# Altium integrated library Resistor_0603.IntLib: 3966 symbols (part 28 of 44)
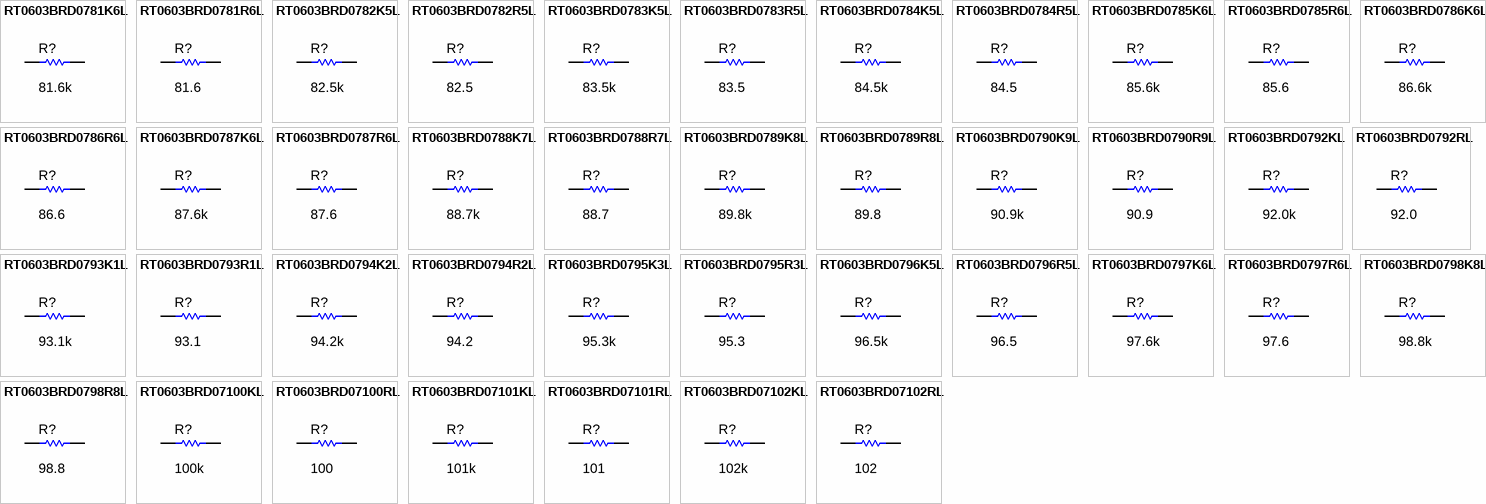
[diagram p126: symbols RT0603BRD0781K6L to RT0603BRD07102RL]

## RT0603BRD0787K6L
designator R?  ValueDisplayed: 87.6k  (hidden comment: RT0603BRD0787K6L)
RES, 87.6 k, 0.1%, 0.1 W, 0603; Manufacturer: Yageo America; CompType: Resistor; Value: 87.6k; Res_ohm: 87600; Value_Code: 87k6; Tolerance_%: 0.1; Value2: 0.1W; VDC_V: 75; TempCo: 25 ppm/C; SizeArea_mm2: 1.28; SizeX_mm: 1.6; SizeY_mm: 0.8; SizeZ_mm: 1; EIA_Code: E192; U/M: EA; AEC Category: Q200
signal-integrity model Resistor
simulation model Resistor
footprint 0603
footprint 0603M
footprint 0603L
footprint 0603_HV
footprint 0603S
pins: 1, 2

## RT0603BRD0787R6L
designator R?  ValueDisplayed: 87.6  (hidden comment: RT0603BRD0787R6L)
RES, 87.6, 0.1%, 0.1 W, 0603; Manufacturer: Yageo America; CompType: Resistor; Value: 87.6; Value_Code: 87R6; Tolerance_%: 0.1; Value2: 0.1W; VDC_V: 75; TempCo: 25 ppm/C; SizeArea_mm2: 1.28; SizeX_mm: 1.6; SizeY_mm: 0.8; SizeZ_mm: 1; EIA_Code: E192; U/M: EA; AEC Category: Q200
signal-integrity model Resistor
simulation model Resistor
footprint 0603
footprint 0603M
footprint 0603L
footprint 0603_HV
footprint 0603S
pins: 1, 2

## RT0603BRD0788K7L
designator R?  ValueDisplayed: 88.7k  (hidden comment: RT0603BRD0788K7L)
RES, 88.7 k, 0.1%, 0.1 W, 0603; Manufacturer: Yageo America; CompType: Resistor; Value: 88.7k; Res_ohm: 88700; Value_Code: 88k7; Tolerance_%: 0.1; Value2: 0.1W; VDC_V: 75; TempCo: 25 ppm/C; SizeArea_mm2: 1.28; SizeX_mm: 1.6; SizeY_mm: 0.8; SizeZ_mm: 1; EIA_Code: E192; U/M: EA; AEC Category: Q200
signal-integrity model Resistor
simulation model Resistor
footprint 0603
footprint 0603M
footprint 0603L
footprint 0603_HV
footprint 0603S
pins: 1, 2

## RT0603BRD0788R7L
designator R?  ValueDisplayed: 88.7  (hidden comment: RT0603BRD0788R7L)
RES, 88.7, 0.1%, 0.1 W, 0603; Manufacturer: Yageo America; CompType: Resistor; Value: 88.7; Value_Code: 88R7; Tolerance_%: 0.1; Value2: 0.1W; VDC_V: 75; TempCo: 25 ppm/C; SizeArea_mm2: 1.28; SizeX_mm: 1.6; SizeY_mm: 0.8; SizeZ_mm: 1; EIA_Code: E192; U/M: EA; AEC Category: Q200
signal-integrity model Resistor
simulation model Resistor
footprint 0603
footprint 0603M
footprint 0603L
footprint 0603_HV
footprint 0603S
pins: 1, 2

## RT0603BRD0789K8L
designator R?  ValueDisplayed: 89.8k  (hidden comment: RT0603BRD0789K8L)
RES, 89.8 k, 0.1%, 0.1 W, 0603; Manufacturer: Yageo America; CompType: Resistor; Value: 89.8k; Res_ohm: 89800; Value_Code: 89k8; Tolerance_%: 0.1; Value2: 0.1W; VDC_V: 75; TempCo: 25 ppm/C; SizeArea_mm2: 1.28; SizeX_mm: 1.6; SizeY_mm: 0.8; SizeZ_mm: 1; EIA_Code: E192; U/M: EA; AEC Category: Q200
signal-integrity model Resistor
simulation model Resistor
footprint 0603
footprint 0603M
footprint 0603L
footprint 0603_HV
footprint 0603S
pins: 1, 2

## RT0603BRD0789R8L
designator R?  ValueDisplayed: 89.8  (hidden comment: RT0603BRD0789R8L)
RES, 89.8, 0.1%, 0.1 W, 0603; Manufacturer: Yageo America; CompType: Resistor; Value: 89.8; Value_Code: 89R8; Tolerance_%: 0.1; Value2: 0.1W; VDC_V: 75; TempCo: 25 ppm/C; SizeArea_mm2: 1.28; SizeX_mm: 1.6; SizeY_mm: 0.8; SizeZ_mm: 1; EIA_Code: E192; U/M: EA; AEC Category: Q200
signal-integrity model Resistor
simulation model Resistor
footprint 0603
footprint 0603M
footprint 0603L
footprint 0603_HV
footprint 0603S
pins: 1, 2

## RT0603BRD0790K9L
designator R?  ValueDisplayed: 90.9k  (hidden comment: RT0603BRD0790K9L)
RES, 90.9 k, 0.1%, 0.1 W, 0603; Manufacturer: Yageo America; CompType: Resistor; Value: 90.9k; Res_ohm: 90900; Value_Code: 90k9; Tolerance_%: 0.1; Value2: 0.1W; VDC_V: 75; TempCo: 25 ppm/C; SizeArea_mm2: 1.28; SizeX_mm: 1.6; SizeY_mm: 0.8; SizeZ_mm: 1; EIA_Code: E192; U/M: EA; AEC Category: Q200
signal-integrity model Resistor
simulation model Resistor
footprint 0603
footprint 0603M
footprint 0603L
footprint 0603_HV
footprint 0603S
pins: 1, 2

## RT0603BRD0790R9L
designator R?  ValueDisplayed: 90.9  (hidden comment: RT0603BRD0790R9L)
RES, 90.9, 0.1%, 0.1 W, 0603; Manufacturer: Yageo America; CompType: Resistor; Value: 90.9; Value_Code: 90R9; Tolerance_%: 0.1; Value2: 0.1W; VDC_V: 75; TempCo: 25 ppm/C; SizeArea_mm2: 1.28; SizeX_mm: 1.6; SizeY_mm: 0.8; SizeZ_mm: 1; EIA_Code: E192; U/M: EA; AEC Category: Q200
signal-integrity model Resistor
simulation model Resistor
footprint 0603
footprint 0603M
footprint 0603L
footprint 0603_HV
footprint 0603S
pins: 1, 2

## RT0603BRD0792KL
designator R?  ValueDisplayed: 92.0k  (hidden comment: RT0603BRD0792KL)
RES, 92.0 k, 0.1%, 0.1 W, 0603; Manufacturer: Yageo America; CompType: Resistor; Value: 92.0k; Res_ohm: 92000; Value_Code: 92k0; Tolerance_%: 0.1; Value2: 0.1W; VDC_V: 75; TempCo: 25 ppm/C; SizeArea_mm2: 1.28; SizeX_mm: 1.6; SizeY_mm: 0.8; SizeZ_mm: 1; EIA_Code: E192; U/M: EA; AEC Category: Q200
signal-integrity model Resistor
simulation model Resistor
footprint 0603
footprint 0603M
footprint 0603L
footprint 0603_HV
footprint 0603S
pins: 1, 2

## RT0603BRD0792RL
designator R?  ValueDisplayed: 92.0  (hidden comment: RT0603BRD0792RL)
RES, 92.0, 0.1%, 0.1 W, 0603; Manufacturer: Yageo America; CompType: Resistor; Value: 92.0; Res_ohm: 92; Value_Code: 92R0; Tolerance_%: 0.1; Value2: 0.1W; VDC_V: 75; TempCo: 25 ppm/C; SizeArea_mm2: 1.28; SizeX_mm: 1.6; SizeY_mm: 0.8; SizeZ_mm: 1; EIA_Code: E192; U/M: EA; AEC Category: Q200
signal-integrity model Resistor
simulation model Resistor
footprint 0603
footprint 0603M
footprint 0603L
footprint 0603_HV
footprint 0603S
pins: 1, 2

## RT0603BRD0793K1L
designator R?  ValueDisplayed: 93.1k  (hidden comment: RT0603BRD0793K1L)
RES, 93.1 k, 0.1%, 0.1 W, 0603; Manufacturer: Yageo America; CompType: Resistor; Value: 93.1k; Res_ohm: 93100; Value_Code: 93k1; Tolerance_%: 0.1; Value2: 0.1W; VDC_V: 75; TempCo: 25 ppm/C; SizeArea_mm2: 1.28; SizeX_mm: 1.6; SizeY_mm: 0.8; SizeZ_mm: 1; EIA_Code: E192; U/M: EA; AEC Category: Q200
signal-integrity model Resistor
simulation model Resistor
footprint 0603
footprint 0603M
footprint 0603L
footprint 0603_HV
footprint 0603S
pins: 1, 2

## RT0603BRD0793R1L
designator R?  ValueDisplayed: 93.1  (hidden comment: RT0603BRD0793R1L)
RES, 93.1, 0.1%, 0.1 W, 0603; Manufacturer: Yageo America; CompType: Resistor; Value: 93.1; Value_Code: 93R1; Tolerance_%: 0.1; Value2: 0.1W; VDC_V: 75; TempCo: 25 ppm/C; SizeArea_mm2: 1.28; SizeX_mm: 1.6; SizeY_mm: 0.8; SizeZ_mm: 1; EIA_Code: E192; U/M: EA; AEC Category: Q200
signal-integrity model Resistor
simulation model Resistor
footprint 0603
footprint 0603M
footprint 0603L
footprint 0603_HV
footprint 0603S
pins: 1, 2

## RT0603BRD0794K2L
designator R?  ValueDisplayed: 94.2k  (hidden comment: RT0603BRD0794K2L)
RES, 94.2 k, 0.1%, 0.1 W, 0603; Manufacturer: Yageo America; CompType: Resistor; Value: 94.2k; Res_ohm: 94200; Value_Code: 94k2; Tolerance_%: 0.1; Value2: 0.1W; VDC_V: 75; TempCo: 25 ppm/C; SizeArea_mm2: 1.28; SizeX_mm: 1.6; SizeY_mm: 0.8; SizeZ_mm: 1; EIA_Code: E192; U/M: EA; AEC Category: Q200
signal-integrity model Resistor
simulation model Resistor
footprint 0603
footprint 0603M
footprint 0603L
footprint 0603_HV
footprint 0603S
pins: 1, 2

## RT0603BRD0794R2L
designator R?  ValueDisplayed: 94.2  (hidden comment: RT0603BRD0794R2L)
RES, 94.2, 0.1%, 0.1 W, 0603; Manufacturer: Yageo America; CompType: Resistor; Value: 94.2; Value_Code: 94R2; Tolerance_%: 0.1; Value2: 0.1W; VDC_V: 75; TempCo: 25 ppm/C; SizeArea_mm2: 1.28; SizeX_mm: 1.6; SizeY_mm: 0.8; SizeZ_mm: 1; EIA_Code: E192; U/M: EA; AEC Category: Q200
signal-integrity model Resistor
simulation model Resistor
footprint 0603
footprint 0603M
footprint 0603L
footprint 0603_HV
footprint 0603S
pins: 1, 2

## RT0603BRD0795K3L
designator R?  ValueDisplayed: 95.3k  (hidden comment: RT0603BRD0795K3L)
RES, 95.3 k, 0.1%, 0.1 W, 0603; Manufacturer: Yageo America; CompType: Resistor; Value: 95.3k; Res_ohm: 95300; Value_Code: 95k3; Tolerance_%: 0.1; Value2: 0.1W; VDC_V: 75; TempCo: 25 ppm/C; SizeArea_mm2: 1.28; SizeX_mm: 1.6; SizeY_mm: 0.8; SizeZ_mm: 1; EIA_Code: E192; U/M: EA; AEC Category: Q200
signal-integrity model Resistor
simulation model Resistor
footprint 0603
footprint 0603M
footprint 0603L
footprint 0603_HV
footprint 0603S
pins: 1, 2

## RT0603BRD0795R3L
designator R?  ValueDisplayed: 95.3  (hidden comment: RT0603BRD0795R3L)
RES, 95.3, 0.1%, 0.1 W, 0603; Manufacturer: Yageo America; CompType: Resistor; Value: 95.3; Value_Code: 95R3; Tolerance_%: 0.1; Value2: 0.1W; VDC_V: 75; TempCo: 25 ppm/C; SizeArea_mm2: 1.28; SizeX_mm: 1.6; SizeY_mm: 0.8; SizeZ_mm: 1; EIA_Code: E192; U/M: EA; AEC Category: Q200
signal-integrity model Resistor
simulation model Resistor
footprint 0603
footprint 0603M
footprint 0603L
footprint 0603_HV
footprint 0603S
pins: 1, 2

## RT0603BRD0796K5L
designator R?  ValueDisplayed: 96.5k  (hidden comment: RT0603BRD0796K5L)
RES, 96.5 k, 0.1%, 0.1 W, 0603; Manufacturer: Yageo America; CompType: Resistor; Value: 96.5k; Res_ohm: 96500; Value_Code: 96k5; Tolerance_%: 0.1; Value2: 0.1W; VDC_V: 75; TempCo: 25 ppm/C; SizeArea_mm2: 1.28; SizeX_mm: 1.6; SizeY_mm: 0.8; SizeZ_mm: 1; EIA_Code: E192; U/M: EA; AEC Category: Q200
signal-integrity model Resistor
simulation model Resistor
footprint 0603
footprint 0603M
footprint 0603L
footprint 0603_HV
footprint 0603S
pins: 1, 2

## RT0603BRD0796R5L
designator R?  ValueDisplayed: 96.5  (hidden comment: RT0603BRD0796R5L)
RES, 96.5, 0.1%, 0.1 W, 0603; Manufacturer: Yageo America; CompType: Resistor; Value: 96.5; Value_Code: 96R5; Tolerance_%: 0.1; Value2: 0.1W; VDC_V: 75; TempCo: 25 ppm/C; SizeArea_mm2: 1.28; SizeX_mm: 1.6; SizeY_mm: 0.8; SizeZ_mm: 1; EIA_Code: E192; U/M: EA; AEC Category: Q200
signal-integrity model Resistor
simulation model Resistor
footprint 0603
footprint 0603M
footprint 0603L
footprint 0603_HV
footprint 0603S
pins: 1, 2

## RT0603BRD0797K6L
designator R?  ValueDisplayed: 97.6k  (hidden comment: RT0603BRD0797K6L)
RES, 97.6 k, 0.1%, 0.1 W, 0603; Manufacturer: Yageo America; CompType: Resistor; Value: 97.6k; Res_ohm: 97600; Value_Code: 97k6; Tolerance_%: 0.1; Value2: 0.1W; VDC_V: 75; TempCo: 25 ppm/C; SizeArea_mm2: 1.28; SizeX_mm: 1.6; SizeY_mm: 0.8; SizeZ_mm: 1; EIA_Code: E192; U/M: EA; AEC Category: Q200
signal-integrity model Resistor
simulation model Resistor
footprint 0603
footprint 0603M
footprint 0603L
footprint 0603_HV
footprint 0603S
pins: 1, 2

## RT0603BRD0797R6L
designator R?  ValueDisplayed: 97.6  (hidden comment: RT0603BRD0797R6L)
RES, 97.6, 0.1%, 0.1 W, 0603; Manufacturer: Yageo America; CompType: Resistor; Value: 97.6; Value_Code: 97R6; Tolerance_%: 0.1; Value2: 0.1W; VDC_V: 75; TempCo: 25 ppm/C; SizeArea_mm2: 1.28; SizeX_mm: 1.6; SizeY_mm: 0.8; SizeZ_mm: 1; EIA_Code: E192; U/M: EA; AEC Category: Q200
signal-integrity model Resistor
simulation model Resistor
footprint 0603
footprint 0603M
footprint 0603L
footprint 0603_HV
footprint 0603S
pins: 1, 2

## RT0603BRD0798K8L
designator R?  ValueDisplayed: 98.8k  (hidden comment: RT0603BRD0798K8L)
RES, 98.8 k, 0.1%, 0.1 W, 0603; Manufacturer: Yageo America; CompType: Resistor; Value: 98.8k; Res_ohm: 98800; Value_Code: 98k8; Tolerance_%: 0.1; Value2: 0.1W; VDC_V: 75; TempCo: 25 ppm/C; SizeArea_mm2: 1.28; SizeX_mm: 1.6; SizeY_mm: 0.8; SizeZ_mm: 1; EIA_Code: E192; U/M: EA; AEC Category: Q200
signal-integrity model Resistor
simulation model Resistor
footprint 0603
footprint 0603M
footprint 0603L
footprint 0603_HV
footprint 0603S
pins: 1, 2

## RT0603BRD0798R8L
designator R?  ValueDisplayed: 98.8  (hidden comment: RT0603BRD0798R8L)
RES, 98.8, 0.1%, 0.1 W, 0603; Manufacturer: Yageo America; CompType: Resistor; Value: 98.8; Value_Code: 98R8; Tolerance_%: 0.1; Value2: 0.1W; VDC_V: 75; TempCo: 25 ppm/C; SizeArea_mm2: 1.28; SizeX_mm: 1.6; SizeY_mm: 0.8; SizeZ_mm: 1; EIA_Code: E192; U/M: EA; AEC Category: Q200
signal-integrity model Resistor
simulation model Resistor
footprint 0603
footprint 0603M
footprint 0603L
footprint 0603_HV
footprint 0603S
pins: 1, 2

## RT0603BRD07100KL
designator R?  ValueDisplayed: 100k  (hidden comment: RT0603BRD07100KL)
RES, 100 k, 0.1%, 0.1 W, 0603; Manufacturer: Yageo America; CompType: Resistor; Value: 100k; Res_ohm: 100000; Tolerance_%: 0.1; Value2: 0.1W; VDC_V: 75; TempCo: 25 ppm/C; SizeArea_mm2: 1.28; SizeX_mm: 1.6; SizeY_mm: 0.8; SizeZ_mm: 1; EIA_Code: E192; U/M: EA; AEC Category: Q200; Green_Lifecycle: Active; Green_REACh: Passed
signal-integrity model Resistor
simulation model Resistor
footprint 0603
footprint 0603M
footprint 0603L
footprint 0603_HV
footprint 0603S
pins: 1, 2

## RT0603BRD07100RL
designator R?  ValueDisplayed: 100  (hidden comment: RT0603BRD07100RL)
RES, 100, 0.1%, 0.1 W, 0603; Manufacturer: Yageo America; CompType: Resistor; Value: 100; Value_Code: 100R; Tolerance_%: 0.1; Value2: 0.1W; VDC_V: 75; TempCo: 25 ppm/C; SizeArea_mm2: 1.28; SizeX_mm: 1.6; SizeY_mm: 0.8; SizeZ_mm: 1; EIA_Code: E192; U/M: EA; AEC Category: Q200
signal-integrity model Resistor
simulation model Resistor
footprint 0603
footprint 0603M
footprint 0603L
footprint 0603_HV
footprint 0603S
pins: 1, 2

## RT0603BRD07101KL
designator R?  ValueDisplayed: 101k  (hidden comment: RT0603BRD07101KL)
RES, 101 k, 0.1%, 0.1 W, 0603; Manufacturer: Yageo America; CompType: Resistor; Value: 101k; Res_ohm: 101000; Tolerance_%: 0.1; Value2: 0.1W; VDC_V: 75; TempCo: 25 ppm/C; SizeArea_mm2: 1.28; SizeX_mm: 1.6; SizeY_mm: 0.8; SizeZ_mm: 1; EIA_Code: E192; U/M: EA; AEC Category: Q200
signal-integrity model Resistor
simulation model Resistor
footprint 0603
footprint 0603M
footprint 0603L
footprint 0603_HV
footprint 0603S
pins: 1, 2

## RT0603BRD07101RL
designator R?  ValueDisplayed: 101  (hidden comment: RT0603BRD07101RL)
RES, 101, 0.1%, 0.1 W, 0603; Manufacturer: Yageo America; CompType: Resistor; Value: 101; Value_Code: 101R; Tolerance_%: 0.1; Value2: 0.1W; VDC_V: 75; TempCo: 25 ppm/C; SizeArea_mm2: 1.28; SizeX_mm: 1.6; SizeY_mm: 0.8; SizeZ_mm: 1; EIA_Code: E192; U/M: EA; AEC Category: Q200
signal-integrity model Resistor
simulation model Resistor
footprint 0603
footprint 0603M
footprint 0603L
footprint 0603_HV
footprint 0603S
pins: 1, 2

## RT0603BRD07102KL
designator R?  ValueDisplayed: 102k  (hidden comment: RT0603BRD07102KL)
RES, 102 k, 0.1%, 0.1 W, 0603; Manufacturer: Yageo America; CompType: Resistor; Value: 102k; Res_ohm: 102000; Tolerance_%: 0.1; Value2: 0.1W; VDC_V: 75; TempCo: 25 ppm/C; SizeArea_mm2: 1.28; SizeX_mm: 1.6; SizeY_mm: 0.8; SizeZ_mm: 1; EIA_Code: E192; U/M: EA; AEC Category: Q200
signal-integrity model Resistor
simulation model Resistor
footprint 0603
footprint 0603M
footprint 0603L
footprint 0603_HV
footprint 0603S
pins: 1, 2

## RT0603BRD07102RL
designator R?  ValueDisplayed: 102  (hidden comment: RT0603BRD07102RL)
RES, 102, 0.1%, 0.1 W, 0603; Manufacturer: Yageo America; CompType: Resistor; Value: 102; Value_Code: 102R; Tolerance_%: 0.1; Value2: 0.1W; VDC_V: 75; TempCo: 25 ppm/C; SizeArea_mm2: 1.28; SizeX_mm: 1.6; SizeY_mm: 0.8; SizeZ_mm: 1; EIA_Code: E192; U/M: EA; AEC Category: Q200
signal-integrity model Resistor
simulation model Resistor
footprint 0603
footprint 0603M
footprint 0603L
footprint 0603_HV
footprint 0603S
pins: 1, 2

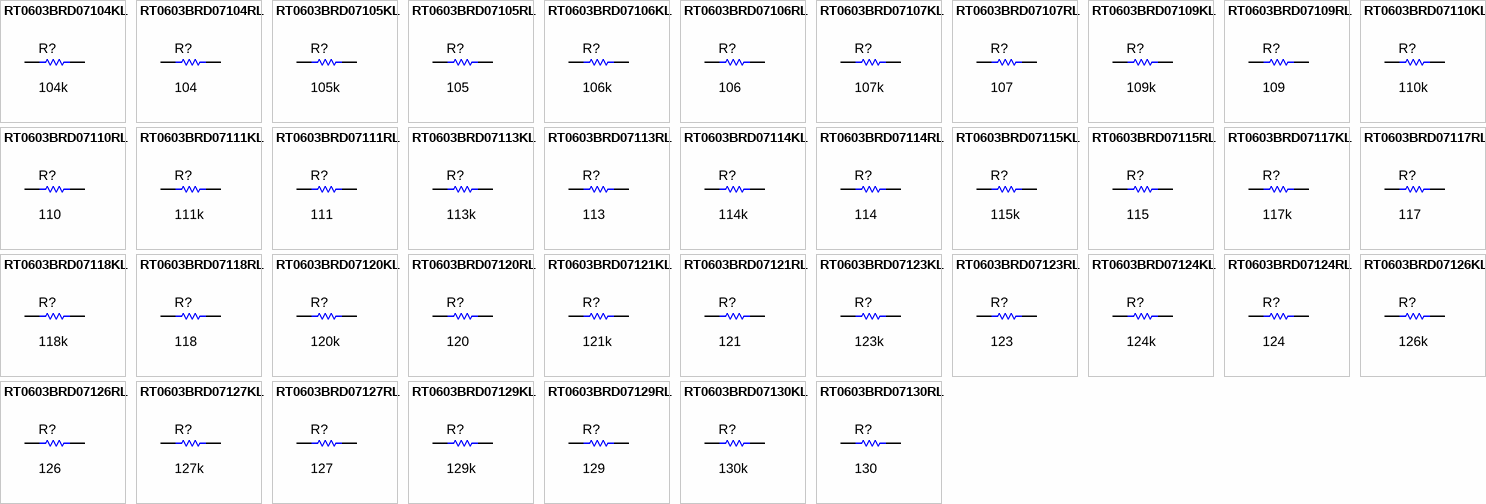
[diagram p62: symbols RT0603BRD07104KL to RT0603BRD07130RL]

## RT0603BRD07104KL
designator R?  ValueDisplayed: 104k  (hidden comment: RT0603BRD07104KL)
RES, 104 k, 0.1%, 0.1 W, 0603; Manufacturer: Yageo America; CompType: Resistor; Value: 104k; Res_ohm: 104000; Tolerance_%: 0.1; Value2: 0.1W; VDC_V: 75; TempCo: 25 ppm/C; SizeArea_mm2: 1.28; SizeX_mm: 1.6; SizeY_mm: 0.8; SizeZ_mm: 1; EIA_Code: E192; U/M: EA; AEC Category: Q200
signal-integrity model Resistor
simulation model Resistor
footprint 0603
footprint 0603M
footprint 0603L
footprint 0603_HV
footprint 0603S
pins: 1, 2

## RT0603BRD07104RL
designator R?  ValueDisplayed: 104  (hidden comment: RT0603BRD07104RL)
RES, 104, 0.1%, 0.1 W, 0603; Manufacturer: Yageo America; CompType: Resistor; Value: 104; Value_Code: 104R; Tolerance_%: 0.1; Value2: 0.1W; VDC_V: 75; TempCo: 25 ppm/C; SizeArea_mm2: 1.28; SizeX_mm: 1.6; SizeY_mm: 0.8; SizeZ_mm: 1; EIA_Code: E192; U/M: EA; AEC Category: Q200
signal-integrity model Resistor
simulation model Resistor
footprint 0603
footprint 0603M
footprint 0603L
footprint 0603_HV
footprint 0603S
pins: 1, 2

## RT0603BRD07105KL
designator R?  ValueDisplayed: 105k  (hidden comment: RT0603BRD07105KL)
RES, 105 k, 0.1%, 0.1 W, 0603; Manufacturer: Yageo America; CompType: Resistor; Value: 105k; Res_ohm: 105000; Tolerance_%: 0.1; Value2: 0.1W; VDC_V: 75; TempCo: 25 ppm/C; SizeArea_mm2: 1.28; SizeX_mm: 1.6; SizeY_mm: 0.8; SizeZ_mm: 1; EIA_Code: E192; U/M: EA; AEC Category: Q200
signal-integrity model Resistor
simulation model Resistor
footprint 0603
footprint 0603M
footprint 0603L
footprint 0603_HV
footprint 0603S
pins: 1, 2

## RT0603BRD07105RL
designator R?  ValueDisplayed: 105  (hidden comment: RT0603BRD07105RL)
RES, 105, 0.1%, 0.1 W, 0603; Manufacturer: Yageo America; CompType: Resistor; Value: 105; Value_Code: 105R; Tolerance_%: 0.1; Value2: 0.1W; VDC_V: 75; TempCo: 25 ppm/C; SizeArea_mm2: 1.28; SizeX_mm: 1.6; SizeY_mm: 0.8; SizeZ_mm: 1; EIA_Code: E192; U/M: EA; AEC Category: Q200
signal-integrity model Resistor
simulation model Resistor
footprint 0603
footprint 0603M
footprint 0603L
footprint 0603_HV
footprint 0603S
pins: 1, 2

## RT0603BRD07106KL
designator R?  ValueDisplayed: 106k  (hidden comment: RT0603BRD07106KL)
RES, 106 k, 0.1%, 0.1 W, 0603; Manufacturer: Yageo America; CompType: Resistor; Value: 106k; Res_ohm: 106000; Tolerance_%: 0.1; Value2: 0.1W; VDC_V: 75; TempCo: 25 ppm/C; SizeArea_mm2: 1.28; SizeX_mm: 1.6; SizeY_mm: 0.8; SizeZ_mm: 1; EIA_Code: E192; U/M: EA; AEC Category: Q200
signal-integrity model Resistor
simulation model Resistor
footprint 0603
footprint 0603M
footprint 0603L
footprint 0603_HV
footprint 0603S
pins: 1, 2

## RT0603BRD07106RL
designator R?  ValueDisplayed: 106  (hidden comment: RT0603BRD07106RL)
RES, 106, 0.1%, 0.1 W, 0603; Manufacturer: Yageo America; CompType: Resistor; Value: 106; Value_Code: 106R; Tolerance_%: 0.1; Value2: 0.1W; VDC_V: 75; TempCo: 25 ppm/C; SizeArea_mm2: 1.28; SizeX_mm: 1.6; SizeY_mm: 0.8; SizeZ_mm: 1; EIA_Code: E192; U/M: EA; AEC Category: Q200
signal-integrity model Resistor
simulation model Resistor
footprint 0603
footprint 0603M
footprint 0603L
footprint 0603_HV
footprint 0603S
pins: 1, 2

## RT0603BRD07107KL
designator R?  ValueDisplayed: 107k  (hidden comment: RT0603BRD07107KL)
RES, 107 k, 0.1%, 0.1 W, 0603; Manufacturer: Yageo America; CompType: Resistor; Value: 107k; Res_ohm: 107000; Tolerance_%: 0.1; Value2: 0.1W; VDC_V: 75; TempCo: 25 ppm/C; SizeArea_mm2: 1.28; SizeX_mm: 1.6; SizeY_mm: 0.8; SizeZ_mm: 1; EIA_Code: E192; U/M: EA; AEC Category: Q200
signal-integrity model Resistor
simulation model Resistor
footprint 0603
footprint 0603M
footprint 0603L
footprint 0603_HV
footprint 0603S
pins: 1, 2

## RT0603BRD07107RL
designator R?  ValueDisplayed: 107  (hidden comment: RT0603BRD07107RL)
RES, 107, 0.1%, 0.1 W, 0603; Manufacturer: Yageo America; CompType: Resistor; Value: 107; Value_Code: 107R; Tolerance_%: 0.1; Value2: 0.1W; VDC_V: 75; TempCo: 25 ppm/C; SizeArea_mm2: 1.28; SizeX_mm: 1.6; SizeY_mm: 0.8; SizeZ_mm: 1; EIA_Code: E192; U/M: EA; AEC Category: Q200
signal-integrity model Resistor
simulation model Resistor
footprint 0603
footprint 0603M
footprint 0603L
footprint 0603_HV
footprint 0603S
pins: 1, 2

## RT0603BRD07109KL
designator R?  ValueDisplayed: 109k  (hidden comment: RT0603BRD07109KL)
RES, 109 k, 0.1%, 0.1 W, 0603; Manufacturer: Yageo America; CompType: Resistor; Value: 109k; Res_ohm: 109000; Tolerance_%: 0.1; Value2: 0.1W; VDC_V: 75; TempCo: 25 ppm/C; SizeArea_mm2: 1.28; SizeX_mm: 1.6; SizeY_mm: 0.8; SizeZ_mm: 1; EIA_Code: E192; U/M: EA; AEC Category: Q200
signal-integrity model Resistor
simulation model Resistor
footprint 0603
footprint 0603M
footprint 0603L
footprint 0603_HV
footprint 0603S
pins: 1, 2

## RT0603BRD07109RL
designator R?  ValueDisplayed: 109  (hidden comment: RT0603BRD07109RL)
RES, 109, 0.1%, 0.1 W, 0603; Manufacturer: Yageo America; CompType: Resistor; Value: 109; Value_Code: 109R; Tolerance_%: 0.1; Value2: 0.1W; VDC_V: 75; TempCo: 25 ppm/C; SizeArea_mm2: 1.28; SizeX_mm: 1.6; SizeY_mm: 0.8; SizeZ_mm: 1; EIA_Code: E192; U/M: EA; AEC Category: Q200
signal-integrity model Resistor
simulation model Resistor
footprint 0603
footprint 0603M
footprint 0603L
footprint 0603_HV
footprint 0603S
pins: 1, 2

## RT0603BRD07110KL
designator R?  ValueDisplayed: 110k  (hidden comment: RT0603BRD07110KL)
RES, 110 k, 0.1%, 0.1 W, 0603; Manufacturer: Yageo America; CompType: Resistor; Value: 110k; Res_ohm: 110000; Tolerance_%: 0.1; Value2: 0.1W; VDC_V: 75; TempCo: 25 ppm/C; SizeArea_mm2: 1.28; SizeX_mm: 1.6; SizeY_mm: 0.8; SizeZ_mm: 1; EIA_Code: E192; U/M: EA; AEC Category: Q200
signal-integrity model Resistor
simulation model Resistor
footprint 0603
footprint 0603M
footprint 0603L
footprint 0603_HV
footprint 0603S
pins: 1, 2

## RT0603BRD07110RL
designator R?  ValueDisplayed: 110  (hidden comment: RT0603BRD07110RL)
RES, 110, 0.1%, 0.1 W, 0603; Manufacturer: Yageo America; CompType: Resistor; Value: 110; Value_Code: 110R; Tolerance_%: 0.1; Value2: 0.1W; VDC_V: 75; TempCo: 25 ppm/C; SizeArea_mm2: 1.28; SizeX_mm: 1.6; SizeY_mm: 0.8; SizeZ_mm: 1; EIA_Code: E192; U/M: EA; AEC Category: Q200
signal-integrity model Resistor
simulation model Resistor
footprint 0603
footprint 0603M
footprint 0603L
footprint 0603_HV
footprint 0603S
pins: 1, 2

## RT0603BRD07111KL
designator R?  ValueDisplayed: 111k  (hidden comment: RT0603BRD07111KL)
RES, 111 k, 0.1%, 0.1 W, 0603; Manufacturer: Yageo America; CompType: Resistor; Value: 111k; Res_ohm: 111000; Tolerance_%: 0.1; Value2: 0.1W; VDC_V: 75; TempCo: 25 ppm/C; SizeArea_mm2: 1.28; SizeX_mm: 1.6; SizeY_mm: 0.8; SizeZ_mm: 1; EIA_Code: E192; U/M: EA; AEC Category: Q200
signal-integrity model Resistor
simulation model Resistor
footprint 0603
footprint 0603M
footprint 0603L
footprint 0603_HV
footprint 0603S
pins: 1, 2

## RT0603BRD07111RL
designator R?  ValueDisplayed: 111  (hidden comment: RT0603BRD07111RL)
RES, 111, 0.1%, 0.1 W, 0603; Manufacturer: Yageo America; CompType: Resistor; Value: 111; Value_Code: 111R; Tolerance_%: 0.1; Value2: 0.1W; VDC_V: 75; TempCo: 25 ppm/C; SizeArea_mm2: 1.28; SizeX_mm: 1.6; SizeY_mm: 0.8; SizeZ_mm: 1; EIA_Code: E192; U/M: EA; AEC Category: Q200
signal-integrity model Resistor
simulation model Resistor
footprint 0603
footprint 0603M
footprint 0603L
footprint 0603_HV
footprint 0603S
pins: 1, 2

## RT0603BRD07113KL
designator R?  ValueDisplayed: 113k  (hidden comment: RT0603BRD07113KL)
RES, 113 k, 0.1%, 0.1 W, 0603; Manufacturer: Yageo America; CompType: Resistor; Value: 113k; Res_ohm: 113000; Tolerance_%: 0.1; Value2: 0.1W; VDC_V: 75; TempCo: 25 ppm/C; SizeArea_mm2: 1.28; SizeX_mm: 1.6; SizeY_mm: 0.8; SizeZ_mm: 1; EIA_Code: E192; U/M: EA; AEC Category: Q200
signal-integrity model Resistor
simulation model Resistor
footprint 0603
footprint 0603M
footprint 0603L
footprint 0603_HV
footprint 0603S
pins: 1, 2

## RT0603BRD07113RL
designator R?  ValueDisplayed: 113  (hidden comment: RT0603BRD07113RL)
RES, 113, 0.1%, 0.1 W, 0603; Manufacturer: Yageo America; CompType: Resistor; Value: 113; Value_Code: 113R; Tolerance_%: 0.1; Value2: 0.1W; VDC_V: 75; TempCo: 25 ppm/C; SizeArea_mm2: 1.28; SizeX_mm: 1.6; SizeY_mm: 0.8; SizeZ_mm: 1; EIA_Code: E192; U/M: EA; AEC Category: Q200
signal-integrity model Resistor
simulation model Resistor
footprint 0603
footprint 0603M
footprint 0603L
footprint 0603_HV
footprint 0603S
pins: 1, 2

## RT0603BRD07114KL
designator R?  ValueDisplayed: 114k  (hidden comment: RT0603BRD07114KL)
RES, 114 k, 0.1%, 0.1 W, 0603; Manufacturer: Yageo America; CompType: Resistor; Value: 114k; Res_ohm: 114000; Tolerance_%: 0.1; Value2: 0.1W; VDC_V: 75; TempCo: 25 ppm/C; SizeArea_mm2: 1.28; SizeX_mm: 1.6; SizeY_mm: 0.8; SizeZ_mm: 1; EIA_Code: E192; U/M: EA; AEC Category: Q200
signal-integrity model Resistor
simulation model Resistor
footprint 0603
footprint 0603M
footprint 0603L
footprint 0603_HV
footprint 0603S
pins: 1, 2

## RT0603BRD07114RL
designator R?  ValueDisplayed: 114  (hidden comment: RT0603BRD07114RL)
RES, 114, 0.1%, 0.1 W, 0603; Manufacturer: Yageo America; CompType: Resistor; Value: 114; Value_Code: 114R; Tolerance_%: 0.1; Value2: 0.1W; VDC_V: 75; TempCo: 25 ppm/C; SizeArea_mm2: 1.28; SizeX_mm: 1.6; SizeY_mm: 0.8; SizeZ_mm: 1; EIA_Code: E192; U/M: EA; AEC Category: Q200
signal-integrity model Resistor
simulation model Resistor
footprint 0603
footprint 0603M
footprint 0603L
footprint 0603_HV
footprint 0603S
pins: 1, 2

## RT0603BRD07115KL
designator R?  ValueDisplayed: 115k  (hidden comment: RT0603BRD07115KL)
RES, 115 k, 0.1%, 0.1 W, 0603; Manufacturer: Yageo America; CompType: Resistor; Value: 115k; Res_ohm: 115000; Tolerance_%: 0.1; Value2: 0.1W; VDC_V: 75; TempCo: 25 ppm/C; SizeArea_mm2: 1.28; SizeX_mm: 1.6; SizeY_mm: 0.8; SizeZ_mm: 1; EIA_Code: E192; U/M: EA; AEC Category: Q200
signal-integrity model Resistor
simulation model Resistor
footprint 0603
footprint 0603M
footprint 0603L
footprint 0603_HV
footprint 0603S
pins: 1, 2

## RT0603BRD07115RL
designator R?  ValueDisplayed: 115  (hidden comment: RT0603BRD07115RL)
RES, 115, 0.1%, 0.1 W, 0603; Manufacturer: Yageo America; CompType: Resistor; Value: 115; Value_Code: 115R; Tolerance_%: 0.1; Value2: 0.1W; VDC_V: 75; TempCo: 25 ppm/C; SizeArea_mm2: 1.28; SizeX_mm: 1.6; SizeY_mm: 0.8; SizeZ_mm: 1; EIA_Code: E192; U/M: EA; AEC Category: Q200
signal-integrity model Resistor
simulation model Resistor
footprint 0603
footprint 0603M
footprint 0603L
footprint 0603_HV
footprint 0603S
pins: 1, 2

## RT0603BRD07117KL
designator R?  ValueDisplayed: 117k  (hidden comment: RT0603BRD07117KL)
RES, 117 k, 0.1%, 0.1 W, 0603; Manufacturer: Yageo America; CompType: Resistor; Value: 117k; Res_ohm: 117000; Tolerance_%: 0.1; Value2: 0.1W; VDC_V: 75; TempCo: 25 ppm/C; SizeArea_mm2: 1.28; SizeX_mm: 1.6; SizeY_mm: 0.8; SizeZ_mm: 1; EIA_Code: E192; U/M: EA; AEC Category: Q200
signal-integrity model Resistor
simulation model Resistor
footprint 0603
footprint 0603M
footprint 0603L
footprint 0603_HV
footprint 0603S
pins: 1, 2

## RT0603BRD07117RL
designator R?  ValueDisplayed: 117  (hidden comment: RT0603BRD07117RL)
RES, 117, 0.1%, 0.1 W, 0603; Manufacturer: Yageo America; CompType: Resistor; Value: 117; Value_Code: 117R; Tolerance_%: 0.1; Value2: 0.1W; VDC_V: 75; TempCo: 25 ppm/C; SizeArea_mm2: 1.28; SizeX_mm: 1.6; SizeY_mm: 0.8; SizeZ_mm: 1; EIA_Code: E192; U/M: EA; AEC Category: Q200
signal-integrity model Resistor
simulation model Resistor
footprint 0603
footprint 0603M
footprint 0603L
footprint 0603_HV
footprint 0603S
pins: 1, 2

## RT0603BRD07118KL
designator R?  ValueDisplayed: 118k  (hidden comment: RT0603BRD07118KL)
RES, 118 k, 0.1%, 0.1 W, 0603; Manufacturer: Yageo America; CompType: Resistor; Value: 118k; Res_ohm: 118000; Tolerance_%: 0.1; Value2: 0.1W; VDC_V: 75; TempCo: 25 ppm/C; SizeArea_mm2: 1.28; SizeX_mm: 1.6; SizeY_mm: 0.8; SizeZ_mm: 1; EIA_Code: E192; U/M: EA; AEC Category: Q200
signal-integrity model Resistor
simulation model Resistor
footprint 0603
footprint 0603M
footprint 0603L
footprint 0603_HV
footprint 0603S
pins: 1, 2

## RT0603BRD07118RL
designator R?  ValueDisplayed: 118  (hidden comment: RT0603BRD07118RL)
RES, 118, 0.1%, 0.1 W, 0603; Manufacturer: Yageo America; CompType: Resistor; Value: 118; Value_Code: 118R; Tolerance_%: 0.1; Value2: 0.1W; VDC_V: 75; TempCo: 25 ppm/C; SizeArea_mm2: 1.28; SizeX_mm: 1.6; SizeY_mm: 0.8; SizeZ_mm: 1; EIA_Code: E192; U/M: EA; AEC Category: Q200
signal-integrity model Resistor
simulation model Resistor
footprint 0603
footprint 0603M
footprint 0603L
footprint 0603_HV
footprint 0603S
pins: 1, 2

## RT0603BRD07120KL
designator R?  ValueDisplayed: 120k  (hidden comment: RT0603BRD07120KL)
RES, 120 k, 0.1%, 0.1 W, 0603; Manufacturer: Yageo America; CompType: Resistor; Value: 120k; Res_ohm: 120000; Tolerance_%: 0.1; Value2: 0.1W; VDC_V: 75; TempCo: 25 ppm/C; SizeArea_mm2: 1.28; SizeX_mm: 1.6; SizeY_mm: 0.8; SizeZ_mm: 1; EIA_Code: E192; U/M: EA; AEC Category: Q200
signal-integrity model Resistor
simulation model Resistor
footprint 0603
footprint 0603M
footprint 0603L
footprint 0603_HV
footprint 0603S
pins: 1, 2

## RT0603BRD07120RL
designator R?  ValueDisplayed: 120  (hidden comment: RT0603BRD07120RL)
RES, 120, 0.1%, 0.1 W, 0603; Manufacturer: Yageo America; CompType: Resistor; Value: 120; Value_Code: 120R; Tolerance_%: 0.1; Value2: 0.1W; VDC_V: 75; TempCo: 25 ppm/C; SizeArea_mm2: 1.28; SizeX_mm: 1.6; SizeY_mm: 0.8; SizeZ_mm: 1; EIA_Code: E192; U/M: EA; AEC Category: Q200
signal-integrity model Resistor
simulation model Resistor
footprint 0603
footprint 0603M
footprint 0603L
footprint 0603_HV
footprint 0603S
pins: 1, 2

## RT0603BRD07121KL
designator R?  ValueDisplayed: 121k  (hidden comment: RT0603BRD07121KL)
RES, 121 k, 0.1%, 0.1 W, 0603; Manufacturer: Yageo America; CompType: Resistor; Value: 121k; Res_ohm: 121000; Tolerance_%: 0.1; Value2: 0.1W; VDC_V: 75; TempCo: 25 ppm/C; SizeArea_mm2: 1.28; SizeX_mm: 1.6; SizeY_mm: 0.8; SizeZ_mm: 1; EIA_Code: E192; U/M: EA; AEC Category: Q200
signal-integrity model Resistor
simulation model Resistor
footprint 0603
footprint 0603M
footprint 0603L
footprint 0603_HV
footprint 0603S
pins: 1, 2

## RT0603BRD07121RL
designator R?  ValueDisplayed: 121  (hidden comment: RT0603BRD07121RL)
RES, 121, 0.1%, 0.1 W, 0603; Manufacturer: Yageo America; CompType: Resistor; Value: 121; Value_Code: 121R; Tolerance_%: 0.1; Value2: 0.1W; VDC_V: 75; TempCo: 25 ppm/C; SizeArea_mm2: 1.28; SizeX_mm: 1.6; SizeY_mm: 0.8; SizeZ_mm: 1; EIA_Code: E192; U/M: EA; AEC Category: Q200
signal-integrity model Resistor
simulation model Resistor
footprint 0603
footprint 0603M
footprint 0603L
footprint 0603_HV
footprint 0603S
pins: 1, 2

## RT0603BRD07123KL
designator R?  ValueDisplayed: 123k  (hidden comment: RT0603BRD07123KL)
RES, 123 k, 0.1%, 0.1 W, 0603; Manufacturer: Yageo America; CompType: Resistor; Value: 123k; Res_ohm: 123000; Tolerance_%: 0.1; Value2: 0.1W; VDC_V: 75; TempCo: 25 ppm/C; SizeArea_mm2: 1.28; SizeX_mm: 1.6; SizeY_mm: 0.8; SizeZ_mm: 1; EIA_Code: E192; U/M: EA; AEC Category: Q200
signal-integrity model Resistor
simulation model Resistor
footprint 0603
footprint 0603M
footprint 0603L
footprint 0603_HV
footprint 0603S
pins: 1, 2

## RT0603BRD07123RL
designator R?  ValueDisplayed: 123  (hidden comment: RT0603BRD07123RL)
RES, 123, 0.1%, 0.1 W, 0603; Manufacturer: Yageo America; CompType: Resistor; Value: 123; Value_Code: 123R; Tolerance_%: 0.1; Value2: 0.1W; VDC_V: 75; TempCo: 25 ppm/C; SizeArea_mm2: 1.28; SizeX_mm: 1.6; SizeY_mm: 0.8; SizeZ_mm: 1; EIA_Code: E192; U/M: EA; AEC Category: Q200
signal-integrity model Resistor
simulation model Resistor
footprint 0603
footprint 0603M
footprint 0603L
footprint 0603_HV
footprint 0603S
pins: 1, 2

## RT0603BRD07124KL
designator R?  ValueDisplayed: 124k  (hidden comment: RT0603BRD07124KL)
RES, 124 k, 0.1%, 0.1 W, 0603; Manufacturer: Yageo America; CompType: Resistor; Value: 124k; Res_ohm: 124000; Tolerance_%: 0.1; Value2: 0.1W; VDC_V: 75; TempCo: 25 ppm/C; SizeArea_mm2: 1.28; SizeX_mm: 1.6; SizeY_mm: 0.8; SizeZ_mm: 1; EIA_Code: E192; U/M: EA; AEC Category: Q200
signal-integrity model Resistor
simulation model Resistor
footprint 0603
footprint 0603M
footprint 0603L
footprint 0603_HV
footprint 0603S
pins: 1, 2

## RT0603BRD07124RL
designator R?  ValueDisplayed: 124  (hidden comment: RT0603BRD07124RL)
RES, 124, 0.1%, 0.1 W, 0603; Manufacturer: Yageo America; CompType: Resistor; Value: 124; Value_Code: 124R; Tolerance_%: 0.1; Value2: 0.1W; VDC_V: 75; TempCo: 25 ppm/C; SizeArea_mm2: 1.28; SizeX_mm: 1.6; SizeY_mm: 0.8; SizeZ_mm: 1; EIA_Code: E192; U/M: EA; AEC Category: Q200
signal-integrity model Resistor
simulation model Resistor
footprint 0603
footprint 0603M
footprint 0603L
footprint 0603_HV
footprint 0603S
pins: 1, 2

## RT0603BRD07126KL
designator R?  ValueDisplayed: 126k  (hidden comment: RT0603BRD07126KL)
RES, 126 k, 0.1%, 0.1 W, 0603; Manufacturer: Yageo America; CompType: Resistor; Value: 126k; Res_ohm: 126000; Tolerance_%: 0.1; Value2: 0.1W; VDC_V: 75; TempCo: 25 ppm/C; SizeArea_mm2: 1.28; SizeX_mm: 1.6; SizeY_mm: 0.8; SizeZ_mm: 1; EIA_Code: E192; U/M: EA; AEC Category: Q200
signal-integrity model Resistor
simulation model Resistor
footprint 0603
footprint 0603M
footprint 0603L
footprint 0603_HV
footprint 0603S
pins: 1, 2

## RT0603BRD07126RL
designator R?  ValueDisplayed: 126  (hidden comment: RT0603BRD07126RL)
RES, 126, 0.1%, 0.1 W, 0603; Manufacturer: Yageo America; CompType: Resistor; Value: 126; Value_Code: 126R; Tolerance_%: 0.1; Value2: 0.1W; VDC_V: 75; TempCo: 25 ppm/C; SizeArea_mm2: 1.28; SizeX_mm: 1.6; SizeY_mm: 0.8; SizeZ_mm: 1; EIA_Code: E192; U/M: EA; AEC Category: Q200
signal-integrity model Resistor
simulation model Resistor
footprint 0603
footprint 0603M
footprint 0603L
footprint 0603_HV
footprint 0603S
pins: 1, 2

## RT0603BRD07127KL
designator R?  ValueDisplayed: 127k  (hidden comment: RT0603BRD07127KL)
RES, 127 k, 0.1%, 0.1 W, 0603; Manufacturer: Yageo America; CompType: Resistor; Value: 127k; Res_ohm: 127000; Tolerance_%: 0.1; Value2: 0.1W; VDC_V: 75; TempCo: 25 ppm/C; SizeArea_mm2: 1.28; SizeX_mm: 1.6; SizeY_mm: 0.8; SizeZ_mm: 1; EIA_Code: E192; U/M: EA; AEC Category: Q200
signal-integrity model Resistor
simulation model Resistor
footprint 0603
footprint 0603M
footprint 0603L
footprint 0603_HV
footprint 0603S
pins: 1, 2

## RT0603BRD07127RL
designator R?  ValueDisplayed: 127  (hidden comment: RT0603BRD07127RL)
RES, 127, 0.1%, 0.1 W, 0603; Manufacturer: Yageo America; CompType: Resistor; Value: 127; Value_Code: 127R; Tolerance_%: 0.1; Value2: 0.1W; VDC_V: 75; TempCo: 25 ppm/C; SizeArea_mm2: 1.28; SizeX_mm: 1.6; SizeY_mm: 0.8; SizeZ_mm: 1; EIA_Code: E192; U/M: EA; AEC Category: Q200
signal-integrity model Resistor
simulation model Resistor
footprint 0603
footprint 0603M
footprint 0603L
footprint 0603_HV
footprint 0603S
pins: 1, 2

## RT0603BRD07129KL
designator R?  ValueDisplayed: 129k  (hidden comment: RT0603BRD07129KL)
RES, 129 k, 0.1%, 0.1 W, 0603; Manufacturer: Yageo America; CompType: Resistor; Value: 129k; Res_ohm: 129000; Tolerance_%: 0.1; Value2: 0.1W; VDC_V: 75; TempCo: 25 ppm/C; SizeArea_mm2: 1.28; SizeX_mm: 1.6; SizeY_mm: 0.8; SizeZ_mm: 1; EIA_Code: E192; U/M: EA; AEC Category: Q200
signal-integrity model Resistor
simulation model Resistor
footprint 0603
footprint 0603M
footprint 0603L
footprint 0603_HV
footprint 0603S
pins: 1, 2

## RT0603BRD07129RL
designator R?  ValueDisplayed: 129  (hidden comment: RT0603BRD07129RL)
RES, 129, 0.1%, 0.1 W, 0603; Manufacturer: Yageo America; CompType: Resistor; Value: 129; Value_Code: 129R; Tolerance_%: 0.1; Value2: 0.1W; VDC_V: 75; TempCo: 25 ppm/C; SizeArea_mm2: 1.28; SizeX_mm: 1.6; SizeY_mm: 0.8; SizeZ_mm: 1; EIA_Code: E192; U/M: EA; AEC Category: Q200
signal-integrity model Resistor
simulation model Resistor
footprint 0603
footprint 0603M
footprint 0603L
footprint 0603_HV
footprint 0603S
pins: 1, 2

## RT0603BRD07130KL
designator R?  ValueDisplayed: 130k  (hidden comment: RT0603BRD07130KL)
RES, 130 k, 0.1%, 0.1 W, 0603; Manufacturer: Yageo America; CompType: Resistor; Value: 130k; Res_ohm: 130000; Tolerance_%: 0.1; Value2: 0.1W; VDC_V: 75; TempCo: 25 ppm/C; SizeArea_mm2: 1.28; SizeX_mm: 1.6; SizeY_mm: 0.8; SizeZ_mm: 1; EIA_Code: E192; U/M: EA; AEC Category: Q200
signal-integrity model Resistor
simulation model Resistor
footprint 0603
footprint 0603M
footprint 0603L
footprint 0603_HV
footprint 0603S
pins: 1, 2

## RT0603BRD07130RL
designator R?  ValueDisplayed: 130  (hidden comment: RT0603BRD07130RL)
RES, 130, 0.1%, 0.1 W, 0603; Manufacturer: Yageo America; CompType: Resistor; Value: 130; Value_Code: 130R; Tolerance_%: 0.1; Value2: 0.1W; VDC_V: 75; TempCo: 25 ppm/C; SizeArea_mm2: 1.28; SizeX_mm: 1.6; SizeY_mm: 0.8; SizeZ_mm: 1; EIA_Code: E192; U/M: EA; AEC Category: Q200
signal-integrity model Resistor
simulation model Resistor
footprint 0603
footprint 0603M
footprint 0603L
footprint 0603_HV
footprint 0603S
pins: 1, 2

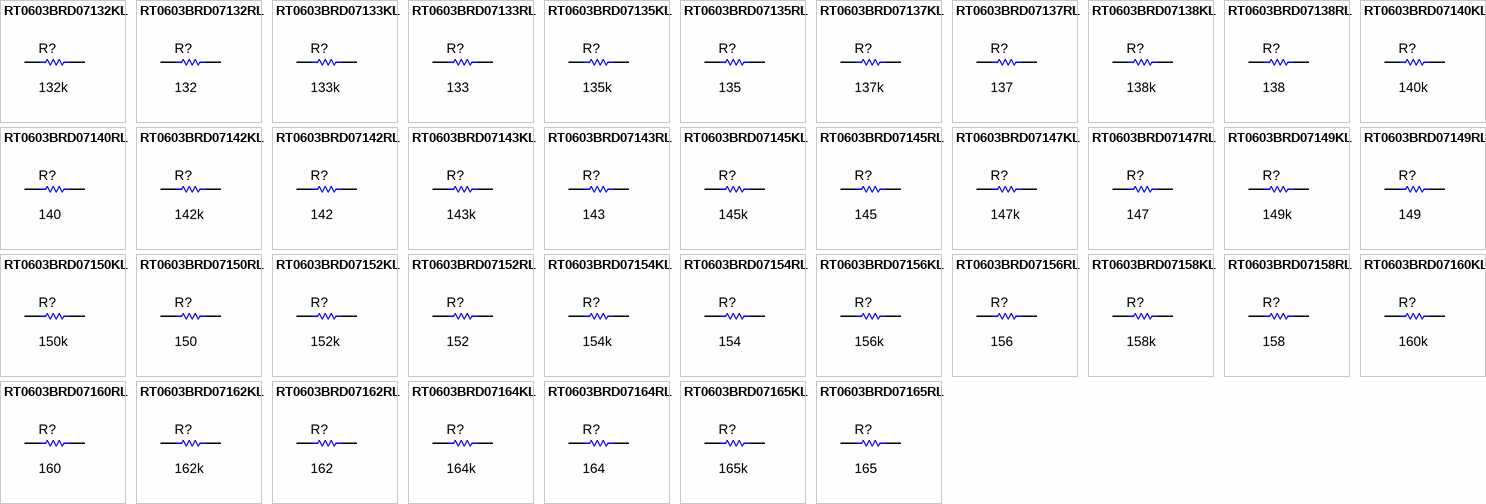
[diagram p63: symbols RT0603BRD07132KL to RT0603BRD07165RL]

## RT0603BRD07132KL
designator R?  ValueDisplayed: 132k  (hidden comment: RT0603BRD07132KL)
RES, 132 k, 0.1%, 0.1 W, 0603; Manufacturer: Yageo America; CompType: Resistor; Value: 132k; Res_ohm: 132000; Tolerance_%: 0.1; Value2: 0.1W; VDC_V: 75; TempCo: 25 ppm/C; SizeArea_mm2: 1.28; SizeX_mm: 1.6; SizeY_mm: 0.8; SizeZ_mm: 1; EIA_Code: E192; U/M: EA; AEC Category: Q200
signal-integrity model Resistor
simulation model Resistor
footprint 0603
footprint 0603M
footprint 0603L
footprint 0603_HV
footprint 0603S
pins: 1, 2

## RT0603BRD07132RL
designator R?  ValueDisplayed: 132  (hidden comment: RT0603BRD07132RL)
RES, 132, 0.1%, 0.1 W, 0603; Manufacturer: Yageo America; CompType: Resistor; Value: 132; Value_Code: 132R; Tolerance_%: 0.1; Value2: 0.1W; VDC_V: 75; TempCo: 25 ppm/C; SizeArea_mm2: 1.28; SizeX_mm: 1.6; SizeY_mm: 0.8; SizeZ_mm: 1; EIA_Code: E192; U/M: EA; AEC Category: Q200
signal-integrity model Resistor
simulation model Resistor
footprint 0603
footprint 0603M
footprint 0603L
footprint 0603_HV
footprint 0603S
pins: 1, 2

## RT0603BRD07133KL
designator R?  ValueDisplayed: 133k  (hidden comment: RT0603BRD07133KL)
RES, 133 k, 0.1%, 0.1 W, 0603; Manufacturer: Yageo America; CompType: Resistor; Value: 133k; Res_ohm: 133000; Tolerance_%: 0.1; Value2: 0.1W; VDC_V: 75; TempCo: 25 ppm/C; SizeArea_mm2: 1.28; SizeX_mm: 1.6; SizeY_mm: 0.8; SizeZ_mm: 1; EIA_Code: E192; U/M: EA; AEC Category: Q200
signal-integrity model Resistor
simulation model Resistor
footprint 0603
footprint 0603M
footprint 0603L
footprint 0603_HV
footprint 0603S
pins: 1, 2

## RT0603BRD07133RL
designator R?  ValueDisplayed: 133  (hidden comment: RT0603BRD07133RL)
RES, 133, 0.1%, 0.1 W, 0603; Manufacturer: Yageo America; CompType: Resistor; Value: 133; Value_Code: 133R; Tolerance_%: 0.1; Value2: 0.1W; VDC_V: 75; TempCo: 25 ppm/C; SizeArea_mm2: 1.28; SizeX_mm: 1.6; SizeY_mm: 0.8; SizeZ_mm: 1; EIA_Code: E192; U/M: EA; AEC Category: Q200
signal-integrity model Resistor
simulation model Resistor
footprint 0603
footprint 0603M
footprint 0603L
footprint 0603_HV
footprint 0603S
pins: 1, 2

## RT0603BRD07135KL
designator R?  ValueDisplayed: 135k  (hidden comment: RT0603BRD07135KL)
RES, 135 k, 0.1%, 0.1 W, 0603; Manufacturer: Yageo America; CompType: Resistor; Value: 135k; Res_ohm: 135000; Tolerance_%: 0.1; Value2: 0.1W; VDC_V: 75; TempCo: 25 ppm/C; SizeArea_mm2: 1.28; SizeX_mm: 1.6; SizeY_mm: 0.8; SizeZ_mm: 1; EIA_Code: E192; U/M: EA; AEC Category: Q200
signal-integrity model Resistor
simulation model Resistor
footprint 0603
footprint 0603M
footprint 0603L
footprint 0603_HV
footprint 0603S
pins: 1, 2

## RT0603BRD07135RL
designator R?  ValueDisplayed: 135  (hidden comment: RT0603BRD07135RL)
RES, 135, 0.1%, 0.1 W, 0603; Manufacturer: Yageo America; CompType: Resistor; Value: 135; Value_Code: 135R; Tolerance_%: 0.1; Value2: 0.1W; VDC_V: 75; TempCo: 25 ppm/C; SizeArea_mm2: 1.28; SizeX_mm: 1.6; SizeY_mm: 0.8; SizeZ_mm: 1; EIA_Code: E192; U/M: EA; AEC Category: Q200
signal-integrity model Resistor
simulation model Resistor
footprint 0603
footprint 0603M
footprint 0603L
footprint 0603_HV
footprint 0603S
pins: 1, 2

## RT0603BRD07137KL
designator R?  ValueDisplayed: 137k  (hidden comment: RT0603BRD07137KL)
RES, 137 k, 0.1%, 0.1 W, 0603; Manufacturer: Yageo America; CompType: Resistor; Value: 137k; Res_ohm: 137000; Tolerance_%: 0.1; Value2: 0.1W; VDC_V: 75; TempCo: 25 ppm/C; SizeArea_mm2: 1.28; SizeX_mm: 1.6; SizeY_mm: 0.8; SizeZ_mm: 1; EIA_Code: E192; U/M: EA; AEC Category: Q200
signal-integrity model Resistor
simulation model Resistor
footprint 0603
footprint 0603M
footprint 0603L
footprint 0603_HV
footprint 0603S
pins: 1, 2

## RT0603BRD07137RL
designator R?  ValueDisplayed: 137  (hidden comment: RT0603BRD07137RL)
RES, 137, 0.1%, 0.1 W, 0603; Manufacturer: Yageo America; CompType: Resistor; Value: 137; Value_Code: 137R; Tolerance_%: 0.1; Value2: 0.1W; VDC_V: 75; TempCo: 25 ppm/C; SizeArea_mm2: 1.28; SizeX_mm: 1.6; SizeY_mm: 0.8; SizeZ_mm: 1; EIA_Code: E192; U/M: EA; AEC Category: Q200
signal-integrity model Resistor
simulation model Resistor
footprint 0603
footprint 0603M
footprint 0603L
footprint 0603_HV
footprint 0603S
pins: 1, 2

## RT0603BRD07138KL
designator R?  ValueDisplayed: 138k  (hidden comment: RT0603BRD07138KL)
RES, 138 k, 0.1%, 0.1 W, 0603; Manufacturer: Yageo America; CompType: Resistor; Value: 138k; Res_ohm: 138000; Tolerance_%: 0.1; Value2: 0.1W; VDC_V: 75; TempCo: 25 ppm/C; SizeArea_mm2: 1.28; SizeX_mm: 1.6; SizeY_mm: 0.8; SizeZ_mm: 1; EIA_Code: E192; U/M: EA; AEC Category: Q200
signal-integrity model Resistor
simulation model Resistor
footprint 0603
footprint 0603M
footprint 0603L
footprint 0603_HV
footprint 0603S
pins: 1, 2

## RT0603BRD07138RL
designator R?  ValueDisplayed: 138  (hidden comment: RT0603BRD07138RL)
RES, 138, 0.1%, 0.1 W, 0603; Manufacturer: Yageo America; CompType: Resistor; Value: 138; Value_Code: 138R; Tolerance_%: 0.1; Value2: 0.1W; VDC_V: 75; TempCo: 25 ppm/C; SizeArea_mm2: 1.28; SizeX_mm: 1.6; SizeY_mm: 0.8; SizeZ_mm: 1; EIA_Code: E192; U/M: EA; AEC Category: Q200
signal-integrity model Resistor
simulation model Resistor
footprint 0603
footprint 0603M
footprint 0603L
footprint 0603_HV
footprint 0603S
pins: 1, 2

## RT0603BRD07140KL
designator R?  ValueDisplayed: 140k  (hidden comment: RT0603BRD07140KL)
RES, 140 k, 0.1%, 0.1 W, 0603; Manufacturer: Yageo America; CompType: Resistor; Value: 140k; Res_ohm: 140000; Tolerance_%: 0.1; Value2: 0.1W; VDC_V: 75; TempCo: 25 ppm/C; SizeArea_mm2: 1.28; SizeX_mm: 1.6; SizeY_mm: 0.8; SizeZ_mm: 1; EIA_Code: E192; U/M: EA; AEC Category: Q200
signal-integrity model Resistor
simulation model Resistor
footprint 0603
footprint 0603M
footprint 0603L
footprint 0603_HV
footprint 0603S
pins: 1, 2

## RT0603BRD07140RL
designator R?  ValueDisplayed: 140  (hidden comment: RT0603BRD07140RL)
RES, 140, 0.1%, 0.1 W, 0603; Manufacturer: Yageo America; CompType: Resistor; Value: 140; Value_Code: 140R; Tolerance_%: 0.1; Value2: 0.1W; VDC_V: 75; TempCo: 25 ppm/C; SizeArea_mm2: 1.28; SizeX_mm: 1.6; SizeY_mm: 0.8; SizeZ_mm: 1; EIA_Code: E192; U/M: EA; AEC Category: Q200
signal-integrity model Resistor
simulation model Resistor
footprint 0603
footprint 0603M
footprint 0603L
footprint 0603_HV
footprint 0603S
pins: 1, 2

## RT0603BRD07142KL
designator R?  ValueDisplayed: 142k  (hidden comment: RT0603BRD07142KL)
RES, 142 k, 0.1%, 0.1 W, 0603; Manufacturer: Yageo America; CompType: Resistor; Value: 142k; Res_ohm: 142000; Tolerance_%: 0.1; Value2: 0.1W; VDC_V: 75; TempCo: 25 ppm/C; SizeArea_mm2: 1.28; SizeX_mm: 1.6; SizeY_mm: 0.8; SizeZ_mm: 1; EIA_Code: E192; U/M: EA; AEC Category: Q200
signal-integrity model Resistor
simulation model Resistor
footprint 0603
footprint 0603M
footprint 0603L
footprint 0603_HV
footprint 0603S
pins: 1, 2

## RT0603BRD07142RL
designator R?  ValueDisplayed: 142  (hidden comment: RT0603BRD07142RL)
RES, 142, 0.1%, 0.1 W, 0603; Manufacturer: Yageo America; CompType: Resistor; Value: 142; Value_Code: 142R; Tolerance_%: 0.1; Value2: 0.1W; VDC_V: 75; TempCo: 25 ppm/C; SizeArea_mm2: 1.28; SizeX_mm: 1.6; SizeY_mm: 0.8; SizeZ_mm: 1; EIA_Code: E192; U/M: EA; AEC Category: Q200
signal-integrity model Resistor
simulation model Resistor
footprint 0603
footprint 0603M
footprint 0603L
footprint 0603_HV
footprint 0603S
pins: 1, 2

## RT0603BRD07143KL
designator R?  ValueDisplayed: 143k  (hidden comment: RT0603BRD07143KL)
RES, 143 k, 0.1%, 0.1 W, 0603; Manufacturer: Yageo America; CompType: Resistor; Value: 143k; Res_ohm: 143000; Tolerance_%: 0.1; Value2: 0.1W; VDC_V: 75; TempCo: 25 ppm/C; SizeArea_mm2: 1.28; SizeX_mm: 1.6; SizeY_mm: 0.8; SizeZ_mm: 1; EIA_Code: E192; U/M: EA; AEC Category: Q200
signal-integrity model Resistor
simulation model Resistor
footprint 0603
footprint 0603M
footprint 0603L
footprint 0603_HV
footprint 0603S
pins: 1, 2

## RT0603BRD07143RL
designator R?  ValueDisplayed: 143  (hidden comment: RT0603BRD07143RL)
RES, 143, 0.1%, 0.1 W, 0603; Manufacturer: Yageo America; CompType: Resistor; Value: 143; Value_Code: 143R; Tolerance_%: 0.1; Value2: 0.1W; VDC_V: 75; TempCo: 25 ppm/C; SizeArea_mm2: 1.28; SizeX_mm: 1.6; SizeY_mm: 0.8; SizeZ_mm: 1; EIA_Code: E192; U/M: EA; AEC Category: Q200
signal-integrity model Resistor
simulation model Resistor
footprint 0603
footprint 0603M
footprint 0603L
footprint 0603_HV
footprint 0603S
pins: 1, 2

## RT0603BRD07145KL
designator R?  ValueDisplayed: 145k  (hidden comment: RT0603BRD07145KL)
RES, 145 k, 0.1%, 0.1 W, 0603; Manufacturer: Yageo America; CompType: Resistor; Value: 145k; Res_ohm: 145000; Tolerance_%: 0.1; Value2: 0.1W; VDC_V: 75; TempCo: 25 ppm/C; SizeArea_mm2: 1.28; SizeX_mm: 1.6; SizeY_mm: 0.8; SizeZ_mm: 1; EIA_Code: E192; U/M: EA; AEC Category: Q200
signal-integrity model Resistor
simulation model Resistor
footprint 0603
footprint 0603M
footprint 0603L
footprint 0603_HV
footprint 0603S
pins: 1, 2

## RT0603BRD07145RL
designator R?  ValueDisplayed: 145  (hidden comment: RT0603BRD07145RL)
RES, 145, 0.1%, 0.1 W, 0603; Manufacturer: Yageo America; CompType: Resistor; Value: 145; Value_Code: 145R; Tolerance_%: 0.1; Value2: 0.1W; VDC_V: 75; TempCo: 25 ppm/C; SizeArea_mm2: 1.28; SizeX_mm: 1.6; SizeY_mm: 0.8; SizeZ_mm: 1; EIA_Code: E192; U/M: EA; AEC Category: Q200
signal-integrity model Resistor
simulation model Resistor
footprint 0603
footprint 0603M
footprint 0603L
footprint 0603_HV
footprint 0603S
pins: 1, 2

## RT0603BRD07147KL
designator R?  ValueDisplayed: 147k  (hidden comment: RT0603BRD07147KL)
RES, 147 k, 0.1%, 0.1 W, 0603; Manufacturer: Yageo America; CompType: Resistor; Value: 147k; Res_ohm: 147000; Tolerance_%: 0.1; Value2: 0.1W; VDC_V: 75; TempCo: 25 ppm/C; SizeArea_mm2: 1.28; SizeX_mm: 1.6; SizeY_mm: 0.8; SizeZ_mm: 1; EIA_Code: E192; U/M: EA; AEC Category: Q200
signal-integrity model Resistor
simulation model Resistor
footprint 0603
footprint 0603M
footprint 0603L
footprint 0603_HV
footprint 0603S
pins: 1, 2

## RT0603BRD07147RL
designator R?  ValueDisplayed: 147  (hidden comment: RT0603BRD07147RL)
RES, 147, 0.1%, 0.1 W, 0603; Manufacturer: Yageo America; CompType: Resistor; Value: 147; Value_Code: 147R; Tolerance_%: 0.1; Value2: 0.1W; VDC_V: 75; TempCo: 25 ppm/C; SizeArea_mm2: 1.28; SizeX_mm: 1.6; SizeY_mm: 0.8; SizeZ_mm: 1; EIA_Code: E192; U/M: EA; AEC Category: Q200
signal-integrity model Resistor
simulation model Resistor
footprint 0603
footprint 0603M
footprint 0603L
footprint 0603_HV
footprint 0603S
pins: 1, 2

## RT0603BRD07149KL
designator R?  ValueDisplayed: 149k  (hidden comment: RT0603BRD07149KL)
RES, 149 k, 0.1%, 0.1 W, 0603; Manufacturer: Yageo America; CompType: Resistor; Value: 149k; Res_ohm: 149000; Tolerance_%: 0.1; Value2: 0.1W; VDC_V: 75; TempCo: 25 ppm/C; SizeArea_mm2: 1.28; SizeX_mm: 1.6; SizeY_mm: 0.8; SizeZ_mm: 1; EIA_Code: E192; U/M: EA; AEC Category: Q200
signal-integrity model Resistor
simulation model Resistor
footprint 0603
footprint 0603M
footprint 0603L
footprint 0603_HV
footprint 0603S
pins: 1, 2

## RT0603BRD07149RL
designator R?  ValueDisplayed: 149  (hidden comment: RT0603BRD07149RL)
RES, 149, 0.1%, 0.1 W, 0603; Manufacturer: Yageo America; CompType: Resistor; Value: 149; Value_Code: 149R; Tolerance_%: 0.1; Value2: 0.1W; VDC_V: 75; TempCo: 25 ppm/C; SizeArea_mm2: 1.28; SizeX_mm: 1.6; SizeY_mm: 0.8; SizeZ_mm: 1; EIA_Code: E192; U/M: EA; AEC Category: Q200
signal-integrity model Resistor
simulation model Resistor
footprint 0603
footprint 0603M
footprint 0603L
footprint 0603_HV
footprint 0603S
pins: 1, 2

## RT0603BRD07150KL
designator R?  ValueDisplayed: 150k  (hidden comment: RT0603BRD07150KL)
RES, 150 k, 0.1%, 0.1 W, 0603; Manufacturer: Yageo America; CompType: Resistor; Value: 150k; Res_ohm: 150000; Tolerance_%: 0.1; Value2: 0.1W; VDC_V: 75; TempCo: 25 ppm/C; SizeArea_mm2: 1.28; SizeX_mm: 1.6; SizeY_mm: 0.8; SizeZ_mm: 1; EIA_Code: E192; U/M: EA; AEC Category: Q200
signal-integrity model Resistor
simulation model Resistor
footprint 0603
footprint 0603M
footprint 0603L
footprint 0603_HV
footprint 0603S
pins: 1, 2

## RT0603BRD07150RL
designator R?  ValueDisplayed: 150  (hidden comment: RT0603BRD07150RL)
RES, 150, 0.1%, 0.1 W, 0603; Manufacturer: Yageo America; CompType: Resistor; Value: 150; Value_Code: 150R; Tolerance_%: 0.1; Value2: 0.1W; VDC_V: 75; TempCo: 25 ppm/C; SizeArea_mm2: 1.28; SizeX_mm: 1.6; SizeY_mm: 0.8; SizeZ_mm: 1; EIA_Code: E192; U/M: EA; AEC Category: Q200
signal-integrity model Resistor
simulation model Resistor
footprint 0603
footprint 0603M
footprint 0603L
footprint 0603_HV
footprint 0603S
pins: 1, 2

## RT0603BRD07152KL
designator R?  ValueDisplayed: 152k  (hidden comment: RT0603BRD07152KL)
RES, 152 k, 0.1%, 0.1 W, 0603; Manufacturer: Yageo America; CompType: Resistor; Value: 152k; Res_ohm: 152000; Tolerance_%: 0.1; Value2: 0.1W; VDC_V: 75; TempCo: 25 ppm/C; SizeArea_mm2: 1.28; SizeX_mm: 1.6; SizeY_mm: 0.8; SizeZ_mm: 1; EIA_Code: E192; U/M: EA; AEC Category: Q200
signal-integrity model Resistor
simulation model Resistor
footprint 0603
footprint 0603M
footprint 0603L
footprint 0603_HV
footprint 0603S
pins: 1, 2

## RT0603BRD07152RL
designator R?  ValueDisplayed: 152  (hidden comment: RT0603BRD07152RL)
RES, 152, 0.1%, 0.1 W, 0603; Manufacturer: Yageo America; CompType: Resistor; Value: 152; Value_Code: 152R; Tolerance_%: 0.1; Value2: 0.1W; VDC_V: 75; TempCo: 25 ppm/C; SizeArea_mm2: 1.28; SizeX_mm: 1.6; SizeY_mm: 0.8; SizeZ_mm: 1; EIA_Code: E192; U/M: EA; AEC Category: Q200
signal-integrity model Resistor
simulation model Resistor
footprint 0603
footprint 0603M
footprint 0603L
footprint 0603_HV
footprint 0603S
pins: 1, 2

## RT0603BRD07154KL
designator R?  ValueDisplayed: 154k  (hidden comment: RT0603BRD07154KL)
RES, 154 k, 0.1%, 0.1 W, 0603; Manufacturer: Yageo America; CompType: Resistor; Value: 154k; Res_ohm: 154000; Tolerance_%: 0.1; Value2: 0.1W; VDC_V: 75; TempCo: 25 ppm/C; SizeArea_mm2: 1.28; SizeX_mm: 1.6; SizeY_mm: 0.8; SizeZ_mm: 1; EIA_Code: E192; U/M: EA; AEC Category: Q200
signal-integrity model Resistor
simulation model Resistor
footprint 0603
footprint 0603M
footprint 0603L
footprint 0603_HV
footprint 0603S
pins: 1, 2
